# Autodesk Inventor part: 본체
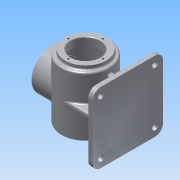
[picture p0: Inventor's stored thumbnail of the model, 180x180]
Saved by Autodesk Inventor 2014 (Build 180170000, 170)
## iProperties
Created: 2015-07
Part Number: 본체
Material: 알루미늄 6061
Document SubType Name: Modeling
Designer: net
Density: 2.71 g/cm^3
Appearance: 알루미늄 - 평지
Mass: 1276.93 g
Surface Area: 1267.31 cm^2
Volume: 471.19 cm^3
Author: net
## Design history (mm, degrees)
sketch "스케치1"
  geometry: C1 r 45 at (0, 0); 1 further point
  constraints: 1 centre point, 1 coincident
  dimensions: "d0" = 90 diameter of C1
extrude "돌출1" new body sketch "스케치1" stored distance "d1" = 110; taper "d2" = 0 deg
sketch "스케치2"
  geometry: C1 r 45 at (0, 0) reference; C2 r 38 at (0, 0)
  constraints: 1 centre point, 1 coincident
  dimensions: "d3" = 76 diameter of C2
extrude "돌출2" join sketch "스케치2" distance "d4" = 7; taper "d5" = 0 deg
sketch "스케치3"
  geometry: C1 r 38 at (0, 0) reference; C2 r 27 at (0, 0)
  constraints: 1 centre point, 1 coincident
  dimensions: "d6" = 54 diameter of C2
extrude "돌출3" cut sketch "스케치3" distance "d7" = 14; taper "d8" = 0 deg
sketch "스케치4"
  geometry: C1 r 40 at (0, 0); 1 further point
  constraints: 1 centre point, 1 coincident
  dimensions: "d9" = 80 diameter of C1
extrude "돌출4" cut sketch "스케치4" stored distance "d10" = 96; taper "d11" = 0 deg
node "작업 평면1"
sketch "스케치5"
  geometry: L1 (-65, 65)-(65, 65); L2 (65, 65)-(65, -65); L3 (65, -65)-(-65, -65); L4 (-65, -65)-(-65, 65); 3 further points
  constraints: 8 end point, 2 midpoint, 2 parallel, 1 horizontal, 1 horizontal alignment, 1 perpendicular, 1 vertical alignment
  dimensions: "d13" = 130 distance of L1.start L1.end; "d14" = 130 distance of L3.end L1.start
extrude "돌출5" join sketch "스케치5" distance "d15" = 10; taper "d16" = 0 deg
sketch "스케치6"
  geometry: L1 (45, 5)-(-45, 5); L2 (-45, 5)-(-45, -5); L3 (-45, -5)-(45, -5); L4 (45, -5)-(45, 5); L5 (5, 45)-(-5, 45); L6 (-5, 45)-(-5, -45); L7 (-5, -45)-(5, -45); L8 (5, -45)-(5, 45); 5 further points
  constraints: 16 end point, 4 midpoint, 4 parallel, 2 horizontal, 2 horizontal alignment, 2 perpendicular, 2 vertical alignment
  dimensions: "d23" = 10 distance between parallel lines of L3 L1; "d24" = 10 distance between parallel lines of L6 L8; "d25" = 90 distance between parallel lines of L2 L4; "d26" = 90 distance between parallel lines of L7 L5
extrude "돌출6" join sketch "스케치6" stored distance "d27" = 10; taper "d28" = 0 deg
fillet "모깎기1" dims "d29" = 15
sketch "스케치7"
  geometry: C1 r 7.5 at (-50, 50); C2 r 7.5 at (50, 50); C3 r 7.5 at (-50, -50); C4 r 7.5 at (50, -50); A1 r 15 centre (-50, 50) between (-50, 65) and (-65, 50) reference; A2 r 15 centre (-50, -50) between (-65, -50) and (-50, -65) reference; A3 r 15 centre (50, -50) between (50, -65) and (65, -50) reference; A4 r 15 centre (50, 50) between (65, 50) and (50, 65) reference; 1 further point
  constraints: 4 centre point, 4 coincident
  dimensions: "d30" = 15 diameter of C1; "d31" = 15 diameter of C2; "d32" = 15 diameter of C3; "d33" = 15 diameter of C4
extrude "돌출7" join sketch "스케치7" distance "d34" = 3; taper "d35" = 0 deg
sketch "스케치8"
  geometry: C1 r 7.5 at (0, 0) reference; C2 r 7.5 at (0, 100) reference; C3 r 7.5 at (100, 100) reference; C4 r 7.5 at (100, 0) reference; 5 further points
  constraints: 4 coincident
hole "구멍1" sketch "스케치8" at (0, 100), (0, 0), (100, 0), (100, 100) diameter "d36" = 10; stored, may be unused: countersink angle "d40" = 90 deg, drill point angle "d42" = 118 deg; dims "d37" = 6, "d38" = 4, "d39" = 2, "d41" = 8
node "작업 평면2"
sketch "스케치9"
  geometry: C1 r 38 at (0, 0); 1 further point
  constraints: 1 centre point, 1 coincident
  dimensions: "d44" = 76 diameter of C1
extrude "돌출8" join sketch "스케치9" stored distance "d45" = 3; taper "d46" = 0 deg
sketch "스케치10"
  geometry: C1 r 38 at (0, 0) reference; C2 r 27 at (0, 0)
  constraints: 1 centre point, 1 coincident
  dimensions: "d47" = 54 diameter of C2
extrude "돌출9" cut sketch "스케치10" stored distance "d48" = 3; taper "d49" = 0 deg
fillet "모깎기2" dims "d50" = 3
sketch "스케치11" dims "d51" = 64
  geometry: C1 r 38 at (0, 0) reference; 2 further points
  constraints: 1 coincident, 1 horizontal alignment, 2 other
hole "구멍2" sketch "스케치11" at (-32, 0) diameter "d52" = 3.242; stored, may be unused: countersink angle "d56" = 90 deg, drill point angle "d58" = 118 deg; dims "d53" = 8, "d54" = 4, "d55" = 2, "d57" = 10
sketch "스케치12" dims "d62" = 64
  geometry: C1 r 38 at (0, 0) reference; 2 further points
  constraints: 1 coincident, 1 vertical alignment, 2 other
hole "구멍3" sketch "스케치12" at (0, 32) diameter "d63" = 3.242; stored, may be unused: countersink angle "d67" = 90 deg, drill point angle "d69" = 118 deg; dims "d64" = 8, "d65" = 4, "d66" = 2, "d68" = 10
chamfer "모따기1" distance "d73" = 1; stored, may be unused: second distance "d74" = 2, angle "d75" = 45 deg
node "작업 평면3"
sketch "스케치13"
  geometry: 2 further points
  constraints: 1 coincident, 1 other
feature "엠보싱1" sketch "스케치13" dims "d1" = 110, "d2" = 0, "d77" = 0.5, "d78" = 0
node "솔리드1"
pattern_circular "원형 패턴1" dims angle "d60" = 360 deg
pattern_circular "원형 패턴2" dims angle "d71" = 360 deg
other parameters: "d12" = 78, "d76" = -55
